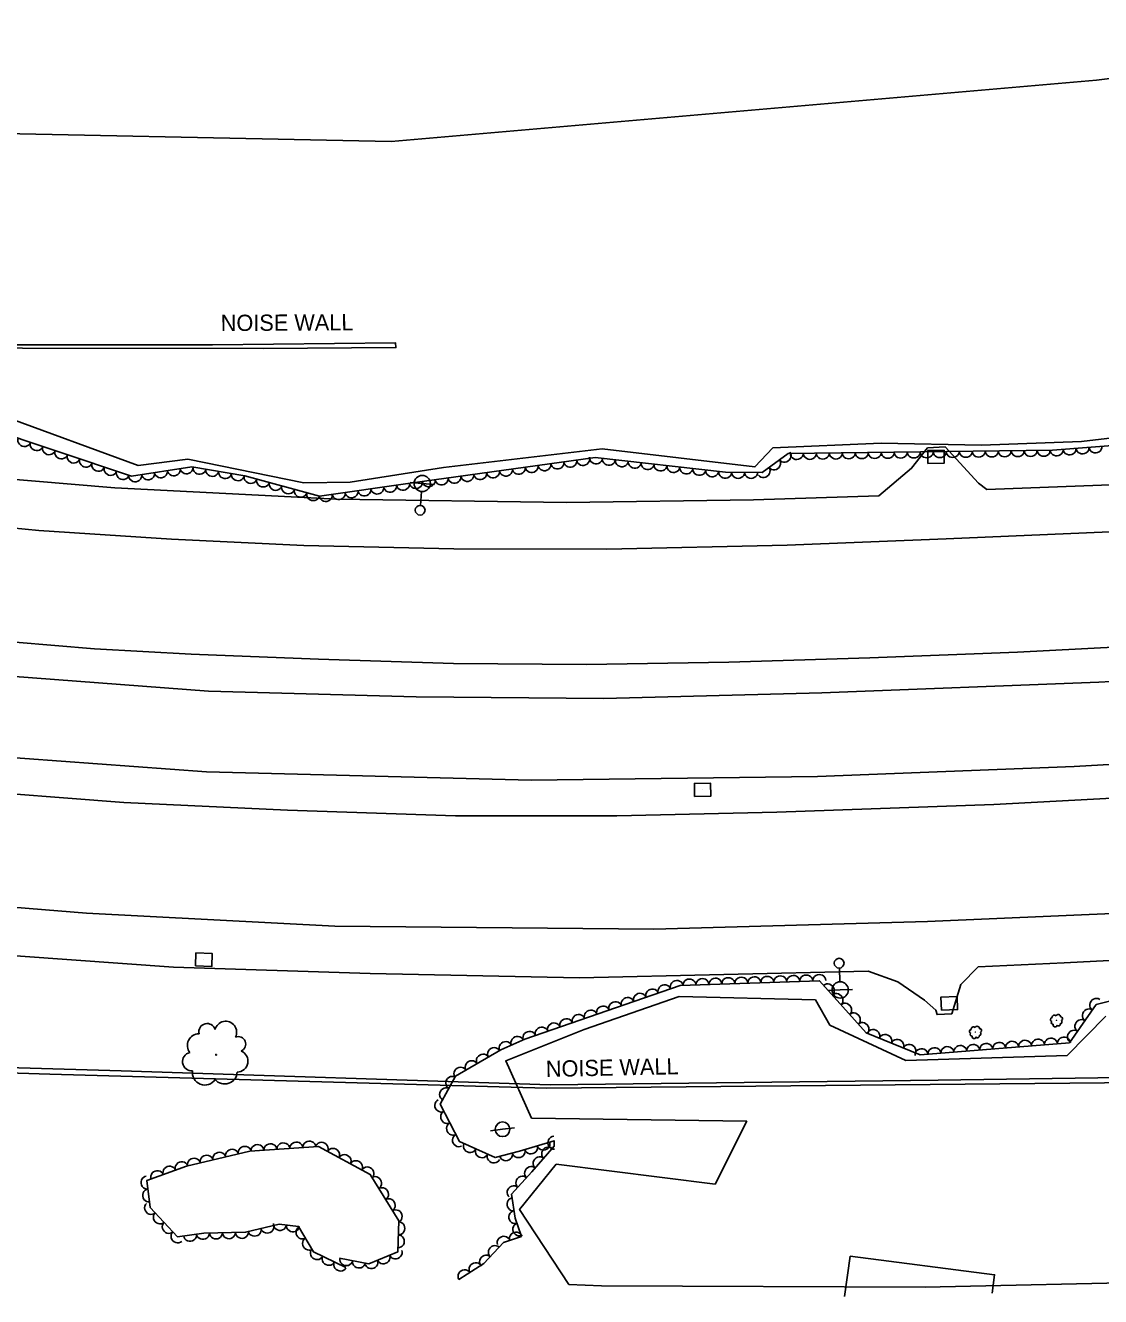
# Model space of a CAD drawing. Extents: x 1722896 to 1754269, y 648279 to 666297.
# Drawn here: x 1733286.4 to 1733617.5, y 649728 to 650119.6 of the extents above; entities that cross this region are included whole.
import ezdxf

# ---------------------------------------------------------------- set-up
doc = ezdxf.new("R2010")
doc.units = 0
for name, color, linetype in [('DESIGN - CENTERLINE - Proposed Text', 7, 'Continuous'), ('DESIGN - SCRATCH - User 1', 7, 'Continuous'), ('SURVEY - CENTERLINE - Preliminary', 7, 'Continuous'), ('SURVEY - CENTERLINE - Preliminary Text', 7, 'Continuous'), ('SURVEY - DRAINAGE - Natural Features', 7, 'Continuous'), ('SURVEY - DTM - Breaklines', 7, 'Continuous'), ('SURVEY - VEGETATION - Features with Text', 7, 'Continuous')]:
    doc.layers.add(name, color=color, linetype=linetype)

msp = doc.modelspace()

# ---------------------------------------------------------------- linework, layer by layer
at = {"layer": 'DESIGN - CENTERLINE - Proposed Text'}
msp.add_lwpolyline([(1733538.71, 649728), (1733540.43, 649740.4), (1733584.91, 649734.73), (1733584.11, 649729.03)], dxfattribs=at)
at = {"layer": 'DESIGN - SCRATCH - User 1'}
for points in [[(1732918.46, 650095.7), (1732990.78, 650071.44), (1733135.5, 650019.64), (1733170.75, 650018.4), (1733238.23, 650012.6), (1733238.7, 650020.63), (1733285.56, 650020.19), (1733359.67, 650020.02), (1733400.55, 650020.36), (1733400.38, 650021.81), (1733344.03, 650021.17), (1733272.52, 650021.18), (1733237.75, 650021.72), (1733237.19, 650014.12), (1733166.92, 650019.66), (1733135.98, 650020.42), (1733079.27, 650040.91), (1732995.25, 650070.89), (1732985.47, 650074.38), (1732919.02, 650097.38), (1732918.46, 650095.7)], [(1733708.07, 649796.67), (1733567.5, 649794.67), (1733447.99, 649793.18), (1733315.88, 649797.53), (1733210.77, 649800.66), (1733125.04, 649822.59), (1733011.58, 649851.6), (1732900.49, 649879.14), (1732799.81, 649904.59), (1732798.94, 649903.11)], [(1732798.94, 649903.11), (1732863.38, 649887.41), (1732951.01, 649865.35), (1733023.96, 649846.89), (1733118.03, 649823.14), (1733212.42, 649799.05), (1733294, 649796.53), (1733446.93, 649792.2), (1733629.48, 649793.9)]]:
    msp.add_lwpolyline(points, dxfattribs=at)
at = {"layer": 'SURVEY - CENTERLINE - Preliminary'}
for points in [[(1733249.81, 650086.9), (1733399.09, 650083.83), (1733616.24, 650102.67), (1733750.82, 650119.57)], [(1733642.17, 649995.02), (1733611.69, 649991.41), (1733580.83, 649990.28), (1733549.92, 649990.87), (1733516.58, 649989.45), (1733511.09, 649983.6), (1733464.01, 649989.19), (1733415.19, 649983.38), (1733386.43, 649978.84), (1733372.14, 649978.7), (1733336.43, 649986.01), (1733321.13, 649984.02), (1733279.13, 649999.38)], [(1733453.74, 649731.7), (1733438.6, 649754.79), (1733449.89, 649768.76), (1733498.81, 649762.64), (1733508.55, 649782.02), (1733442.33, 649783.01), (1733434.34, 649800.59), (1733458.46, 649810.3), (1733487.73, 649820.4), (1733529.7, 649819.44), (1733534.17, 649811.64), (1733557.55, 649800.75), (1733607.23, 649802.24), (1733619.14, 649814.38)], [(1733712.81, 649734.17), (1733563.48, 649730.91), (1733463.86, 649731.35), (1733453.74, 649731.7)]]:
    msp.add_lwpolyline(points, dxfattribs=at)
at = {"layer": 'SURVEY - CENTERLINE - Preliminary Text'}
for points in [[(1732884.23, 650076.17), (1732913.51, 650063.39), (1732976.87, 650040.9), (1733026.18, 650025.83), (1733038.06, 650031.39), (1733045.75, 650036.92), (1733051.82, 650034.88), (1733060.67, 650016.94), (1733102.57, 650006.66), (1733179.26, 649991.5), (1733218.23, 649985.76), (1733263.82, 649981.38), (1733313.93, 649977.09), (1733382.39, 649973.59), (1733453.08, 649972.61), (1733510.66, 649973.39), (1733549.29, 649974.69), (1733559.34, 649983.17), (1733564.28, 649989.43), (1733569.64, 649989.78), (1733579.99, 649978.6), (1733582.55, 649976.61), (1733628.65, 649978.32)], [(1733632.4, 649964.05), (1733569.97, 649961.42), (1733520.99, 649959.49), (1733465.51, 649958.19), (1733418.34, 649958.38), (1733372.14, 649959.4), (1733331.39, 649961.34), (1733290.54, 649963.98), (1733252.55, 649967.68), (1733214.23, 649972.07), (1733176.01, 649978.17), (1733138.91, 649984.71), (1733111.59, 649989.86), (1733075.7, 649997.91), (1733042.53, 650006.26), (1733001.92, 650017.92), (1732980.45, 650024.43), (1732948.58, 650035.49), (1732913.65, 650048.13), (1732876.04, 650062.89)], [(1734301.81, 649956.07), (1734220.48, 649950.88), (1734131.61, 649945.81), (1734021.54, 649939.36), (1733919.47, 649934.02), (1733832.29, 649929.05), (1733727.11, 649923.18), (1733616.99, 649917.25), (1733531.68, 649913.99), (1733464.56, 649912.26), (1733406.75, 649912.72), (1733342.81, 649914.54), (1733274.96, 649919.59), (1733238.81, 649922.74), (1733185.09, 649929.55), (1733133.9, 649938.69), (1733073.43, 649951.76), (1733022.34, 649964.08), (1732970.97, 649979.26), (1732924.79, 649995.09), (1732879.46, 650012.26), (1732856.98, 650021.29), (1732850.17, 650024.36)], [(1732910.74, 650011.51), (1732938.88, 650001.25), (1732978.51, 649988.35), (1733017.77, 649976.28), (1733057.36, 649966.4), (1733089.54, 649958.9), (1733122.15, 649951.97), (1733160.83, 649944.57), (1733191.08, 649940.04), (1733225.38, 649935.66), (1733270.98, 649930.64), (1733307.72, 649927.55), (1733337.44, 649925.94), (1733376.66, 649924.33), (1733418.23, 649922.99), (1733459.22, 649922.73), (1733503.07, 649923.42), (1733546.45, 649924.78), (1733592, 649926.51), (1733633.36, 649928.65)], [(1734306.6, 649930.59), (1734223.76, 649925.97), (1734108.71, 649919.44), (1734005.23, 649913.81), (1733895.38, 649907.1), (1733786.65, 649900.93), (1733684.61, 649895.58), (1733609.37, 649891.26), (1733530.4, 649888.22), (1733442.22, 649887.03), (1733342.17, 649889.65), (1733241.37, 649897), (1733146.01, 649910.52), (1733060.2, 649928.54), (1732976.3, 649951.63), (1732924.93, 649968.37), (1732878.63, 649985.6), (1732846.43, 649998.22), (1732835.13, 650003.3)], [(1732828.72, 649994.26), (1732832.8, 649992.38), (1732898.27, 649967.02), (1732935.22, 649953.75), (1732972.35, 649941.94), (1733018.58, 649928.26), (1733075.49, 649914.12), (1733116.55, 649905.32), (1733166.7, 649896.35), (1733213.16, 649889.74), (1733263.56, 649884.35), (1733316.73, 649880.2), (1733367.1, 649877.8), (1733418.88, 649876.14), (1733468.6, 649876.11), (1733517.84, 649877.2), (1733584.68, 649879.55), (1733659.52, 649883.6)], [(1734316.03, 649884.62), (1734227.04, 649879.8), (1734116.98, 649873.99), (1734008.92, 649867.44), (1733915.96, 649862.48), (1733822.6, 649857.33), (1733730.22, 649851.85), (1733644.88, 649847.07), (1733564.26, 649843.52), (1733479.91, 649841.18), (1733381.77, 649842.06), (1733305.26, 649846.16), (1733233.28, 649851.95), (1733189.33, 649857.53), (1733142.07, 649864.89), (1733082.71, 649876.45), (1733033.05, 649888.27), (1732982.37, 649901.96), (1732935.11, 649916.49), (1732876.61, 649937.35), (1732823.05, 649958.66), (1732808.59, 649965.1)], [(1732801.64, 649952.87), (1732820.37, 649944.25), (1732867.75, 649925.97), (1732908.14, 649911.21), (1732946.71, 649898.3), (1732999.39, 649882.77), (1733034.4, 649873.67), (1733105, 649857.11), (1733171.98, 649845.25), (1733226.84, 649838.36), (1733269.1, 649834.02), (1733332.07, 649829.44), (1733392.65, 649827.49), (1733457.05, 649826.23), (1733545.96, 649828.27), (1733555.15, 649824.91), (1733563.28, 649819.35), (1733566.84, 649816.28), (1733567.21, 649814.86), (1733571.69, 649815.15), (1733574.47, 649824.18), (1733579.83, 649829.56), (1733606.32, 649830.82), (1733646.3, 649832.85)]]:
    msp.add_lwpolyline(points, dxfattribs=at)
at = {"layer": 'SURVEY - DRAINAGE - Natural Features'}
for p, q in [((1733566.85, 649986.67), (1733566.85, 649986.67)), ((1733494.96, 649884.12), (1733494.96, 649884.12)), ((1733341.41, 649831.8), (1733341.41, 649831.8)), ((1733570.93, 649818.32), (1733570.93, 649818.32))]:
    msp.add_line(p, q, dxfattribs=at)
for points in [[(1733564.36, 649984.66), (1733564.34, 649988.66), (1733569.34, 649988.69), (1733569.36, 649984.69), (1733564.36, 649984.66)], [(1733492.49, 649882.09), (1733492.44, 649886.09), (1733497.44, 649886.15), (1733497.49, 649882.15), (1733492.49, 649882.09)], [(1733338.86, 649829.86), (1733338.96, 649833.86), (1733343.95, 649833.73), (1733343.86, 649829.73), (1733338.86, 649829.86)], [(1733568.51, 649816.21), (1733568.34, 649820.21), (1733573.34, 649820.42), (1733573.51, 649816.43), (1733568.51, 649816.21)]]:
    msp.add_lwpolyline(points, dxfattribs=at)
at = {"layer": 'SURVEY - DTM - Breaklines'}
for p, q in [((1733408.64, 649978.47), (1733404.9, 649978.76)), ((1733408.64, 649978.47), (1733412.38, 649978.18)), ((1733408.11, 649971.74), (1733408.44, 649975.98)), ((1733537.09, 649829.21), (1733537.25, 649824.96)), ((1733537.35, 649822.46), (1733533.6, 649822.32)), ((1733537.35, 649822.46), (1733541.1, 649822.61)), ((1733433.36, 649779.54), (1733429.64, 649779.11)), ((1733433.36, 649779.54), (1733437.09, 649779.97))]:
    msp.add_line(p, q, dxfattribs=at)
for centre, radius in [((1733408.64, 649978.47), 2.5), ((1733408, 649970.24), 1.5), ((1733537.03, 649830.7), 1.5), ((1733537.35, 649822.46), 2.5), ((1733433.36, 649779.54), 2.25)]:
    msp.add_circle(centre, radius, dxfattribs=at)
at = {"layer": 'SURVEY - VEGETATION - Features with Text'}
for points in [[(1733625.2, 649990.47), (1733602.68, 649988.77), (1733521.3, 649987.7), (1733513.3, 649981.88), (1733502.06, 649981.96), (1733461.89, 649986.43), (1733404.91, 649978.56), (1733377, 649974.53), (1733354.04, 649980.84), (1733337.68, 649983.59), (1733319.07, 649980.7), (1733273.29, 649996.05)], [(1733419.95, 649733.28), (1733427.6, 649738.18), (1733433.64, 649744.66), (1733439.16, 649746.55), (1733437.25, 649752.19), (1733436.16, 649759.55), (1733442.39, 649766.45), (1733449.31, 649774.34), (1733449.22, 649776.01), (1733438.55, 649772.77), (1733431.1, 649770.84), (1733420.07, 649775.73), (1733414.21, 649787.23), (1733418.9, 649795.9), (1733432.8, 649803.97), (1733440.22, 649807.3), (1733488.12, 649823.84), (1733530.99, 649825.31), (1733545.37, 649809.26), (1733561.95, 649802.44), (1733607.96, 649806.2), (1733616.2, 649818), (1733633.54, 649822.28)], [(1733385.16, 649736.91), (1733375.15, 649741.79), (1733370.58, 649749.63), (1733364.58, 649750.3), (1733354.23, 649747.82), (1733341.43, 649747.55), (1733333.32, 649746.38), (1733324.89, 649755.44), (1733323.83, 649763.72), (1733336.06, 649768.2), (1733355.56, 649772.77), (1733376.67, 649774.19), (1733392.61, 649765.61), (1733401.44, 649751.3), (1733401.12, 649741.75), (1733392.16, 649738.14), (1733383.18, 649739.79)]]:
    msp.add_lwpolyline(points, dxfattribs=at)
for centre, radius in [((1733603.95, 649813.08), 0.022), ((1733579.01, 649809.44), 0.022), ((1733345.16, 649802.49), 0.118)]:
    msp.add_circle(centre, radius, dxfattribs=at)
for centre, radius, start, end in [((1733342.4, 649809.55), 2.56, 15.5791, 192.8983), ((1733348.13, 649809.45), 3.36, 332.9604, 166.3801), ((1733602.71, 649813.31), 0.631, 97.432, 254.221), ((1733602.75, 649812.33), 0.433, 119.5482, 298.2938), ((1733603.34, 649813.99), 0.719, 46.4848, 184.009), ((1733604.47, 649814.19), 0.714, 357.3806, 153.2191), ((1733604.98, 649812.66), 0.679, 277.4746, 44.3203), ((1733605.3, 649813.64), 0.527, 287.6335, 102.6338), ((1733339.96, 649805.36), 3.63, 90.8662, 217.7118), ((1733577.77, 649809.67), 0.631, 97.432, 254.221), ((1733577.81, 649808.68), 0.433, 119.5482, 298.2938), ((1733578.4, 649810.34), 0.719, 46.4848, 184.009), ((1733578.6, 649808.08), 0.629, 159.5689, 352.9886), ((1733579.53, 649810.54), 0.714, 357.3806, 153.2191), ((1733579.67, 649808.18), 0.479, 202.1876, 19.5067), ((1733580.03, 649809.02), 0.679, 277.4746, 44.3203), ((1733580.36, 649809.99), 0.527, 287.6335, 102.6338), ((1733603.54, 649811.73), 0.629, 159.5689, 352.9886), ((1733604.61, 649811.83), 0.479, 202.1876, 19.5067), ((1733351.98, 649805.77), 2.31, 292.9398, 111.6854), ((1733337.62, 649800.38), 2.81, 101.0251, 276.0254), ((1733351.6, 649800.52), 3.37, 270.8236, 67.6125), ((1733341.69, 649796.97), 3.82, 170.7722, 326.6107), ((1733347.82, 649797.33), 3.84, 219.8763, 357.4006)]:
    msp.add_arc(centre, radius, start, end, dxfattribs=at)
for centre, major_axis in [((1733286.09, 649991.76), (-1.9, 0.64)), ((1733289.88, 649990.49), (-1.9, 0.64)), ((1733293.68, 649989.22), (-1.9, 0.64)), ((1733297.47, 649987.95), (-1.9, 0.64)), ((1733564.01, 649988.26), (-2, -0.03)), ((1733568.01, 649988.31), (-2, -0.03)), ((1733572.01, 649988.37), (-2, -0.03)), ((1733576.01, 649988.42), (-2, -0.03)), ((1733580.01, 649988.47), (-2, -0.03)), ((1733584.01, 649988.52), (-2, -0.03)), ((1733588.01, 649988.58), (-2, -0.03)), ((1733592.01, 649988.63), (-2, -0.03)), ((1733596.01, 649988.68), (-2, -0.03)), ((1733600.01, 649988.73), (-2, -0.03)), ((1733604.01, 649988.87), (-1.99, -0.15)), ((1733607.99, 649989.17), (-1.99, -0.15)), ((1733611.98, 649989.47), (-1.99, -0.15)), ((1733615.97, 649989.77), (-1.99, -0.15)), ((1733301.26, 649986.67), (-1.9, 0.64)), ((1733305.05, 649985.4), (-1.9, 0.64)), ((1733308.85, 649984.13), (-1.9, 0.64)), ((1733446.3, 649984.27), (-1.98, -0.27)), ((1733450.27, 649984.82), (-1.98, -0.27)), ((1733454.23, 649985.37), (-1.98, -0.27)), ((1733458.19, 649985.91), (-1.98, -0.27)), ((1733462.15, 649986.4), (-1.99, 0.22)), ((1733466.13, 649985.95), (-1.99, 0.22)), ((1733470.1, 649985.51), (-1.99, 0.22)), ((1733474.08, 649985.07), (-1.99, 0.22)), ((1733478.06, 649984.63), (-1.99, 0.22)), ((1733482.03, 649984.19), (-1.99, 0.22)), ((1733517.03, 649984.59), (-1.62, -1.18)), ((1733520.26, 649986.95), (-1.62, -1.18)), ((1733524.02, 649987.73), (-2, -0.03)), ((1733528.02, 649987.79), (-2, -0.03)), ((1733532.02, 649987.84), (-2, -0.03)), ((1733536.02, 649987.89), (-2, -0.03)), ((1733540.01, 649987.95), (-2, -0.03)), ((1733544.01, 649988), (-2, -0.03)), ((1733548.01, 649988.05), (-2, -0.03)), ((1733552.01, 649988.1), (-2, -0.03)), ((1733556.01, 649988.16), (-2, -0.03)), ((1733560.01, 649988.21), (-2, -0.03)), ((1733312.64, 649982.86), (-1.9, 0.64)), ((1733316.43, 649981.59), (-1.9, 0.64)), ((1733320.27, 649980.89), (-1.98, -0.31)), ((1733324.23, 649981.5), (-1.98, -0.31)), ((1733328.18, 649982.12), (-1.98, -0.31)), ((1733332.13, 649982.73), (-1.98, -0.31)), ((1733336.08, 649983.35), (-1.98, -0.31)), ((1733340.03, 649983.2), (-1.97, 0.33)), ((1733343.98, 649982.53), (-1.97, 0.33)), ((1733347.92, 649981.87), (-1.97, 0.33)), ((1733351.86, 649981.2), (-1.97, 0.33)), ((1733355.77, 649980.36), (-1.93, 0.53)), ((1733418.57, 649980.45), (-1.98, -0.27)), ((1733422.53, 649980.99), (-1.98, -0.27)), ((1733426.49, 649981.54), (-1.98, -0.27)), ((1733430.45, 649982.09), (-1.98, -0.27)), ((1733434.42, 649982.63), (-1.98, -0.27)), ((1733438.38, 649983.18), (-1.98, -0.27)), ((1733442.34, 649983.73), (-1.98, -0.27)), ((1733486.01, 649983.74), (-1.99, 0.22)), ((1733489.98, 649983.3), (-1.99, 0.22)), ((1733493.96, 649982.86), (-1.99, 0.22)), ((1733497.93, 649982.42), (-1.99, 0.22)), ((1733501.91, 649981.98), (-1.99, 0.22)), ((1733505.91, 649981.93), (-2, 0.01)), ((1733509.91, 649981.91), (-2, 0.01)), ((1733513.79, 649982.24), (-1.62, -1.18)), ((1733359.63, 649979.3), (-1.93, 0.53)), ((1733363.48, 649978.25), (-1.93, 0.53)), ((1733367.34, 649977.19), (-1.93, 0.53)), ((1733371.2, 649976.13), (-1.93, 0.53)), ((1733390.84, 649976.53), (-1.98, -0.29)), ((1733394.8, 649977.1), (-1.98, -0.29)), ((1733398.76, 649977.67), (-1.98, -0.29)), ((1733402.72, 649978.24), (-1.98, -0.29)), ((1733406.68, 649978.8), (-1.98, -0.27)), ((1733410.64, 649979.35), (-1.98, -0.27)), ((1733414.6, 649979.9), (-1.98, -0.27)), ((1733375.06, 649975.07), (-1.93, 0.53)), ((1733378.96, 649974.82), (-1.98, -0.29)), ((1733382.92, 649975.39), (-1.98, -0.29)), ((1733386.88, 649975.96), (-1.98, -0.29)), ((1733483.22, 649822.15), (1.89, 0.65)), ((1733487, 649823.46), (1.89, 0.65)), ((1733490.93, 649823.94), (2, 0.07)), ((1733494.93, 649824.08), (2, 0.07)), ((1733498.93, 649824.21), (2, 0.07)), ((1733502.92, 649824.35), (2, 0.07)), ((1733506.92, 649824.49), (2, 0.07)), ((1733510.92, 649824.62), (2, 0.07)), ((1733514.92, 649824.76), (2, 0.07)), ((1733518.91, 649824.89), (2, 0.07)), ((1733522.91, 649825.03), (2, 0.07)), ((1733526.91, 649825.17), (2, 0.07)), ((1733530.91, 649825.3), (2, 0.07)), ((1733533.6, 649822.39), (1.33, -1.49)), ((1733471.87, 649818.23), (1.89, 0.65)), ((1733475.65, 649819.54), (1.89, 0.65)), ((1733479.44, 649820.85), (1.89, 0.65)), ((1733536.27, 649819.41), (1.33, -1.49)), ((1733616.13, 649817.91), (1.15, 1.64)), ((1733460.53, 649814.32), (1.89, 0.65)), ((1733464.31, 649815.62), (1.89, 0.65)), ((1733468.09, 649816.93), (1.89, 0.65)), ((1733538.94, 649816.43), (1.33, -1.49)), ((1733613.84, 649814.63), (1.15, 1.64)), ((1733449.19, 649810.4), (1.89, 0.65)), ((1733452.97, 649811.7), (1.89, 0.65)), ((1733456.75, 649813.01), (1.89, 0.65)), ((1733541.61, 649813.45), (1.33, -1.49)), ((1733544.28, 649810.47), (1.33, -1.49)), ((1733611.55, 649811.35), (1.15, 1.64)), ((1733437.93, 649806.27), (1.82, 0.82)), ((1733441.63, 649807.79), (1.89, 0.65)), ((1733445.41, 649809.09), (1.89, 0.65)), ((1733547.56, 649808.36), (1.85, -0.76)), ((1733551.26, 649806.84), (1.85, -0.76)), ((1733609.26, 649808.07), (1.15, 1.64)), ((1733430.74, 649802.78), (1.73, 1.01)), ((1733434.28, 649804.64), (1.82, 0.82)), ((1733554.96, 649805.31), (1.85, -0.76)), ((1733558.66, 649803.79), (1.85, -0.76)), ((1733562.39, 649802.47), (1.99, 0.16)), ((1733566.38, 649802.8), (1.99, 0.16)), ((1733570.37, 649803.12), (1.99, 0.16)), ((1733574.35, 649803.45), (1.99, 0.16)), ((1733578.34, 649803.78), (1.99, 0.16)), ((1733582.33, 649804.1), (1.99, 0.16)), ((1733586.31, 649804.43), (1.99, 0.16)), ((1733590.3, 649804.76), (1.99, 0.16)), ((1733594.29, 649805.08), (1.99, 0.16)), ((1733598.27, 649805.41), (1.99, 0.16)), ((1733602.26, 649805.73), (1.99, 0.16)), ((1733606.25, 649806.06), (1.99, 0.16)), ((1733423.83, 649798.76), (1.73, 1.01)), ((1733427.28, 649800.77), (1.73, 1.01)), ((1733420.37, 649796.75), (1.73, 1.01)), ((1733415.9, 649790.35), (0.95, 1.76)), ((1733417.8, 649793.87), (0.95, 1.76)), ((1733414.41, 649786.83), (-0.91, 1.78)), ((1733416.23, 649783.27), (-0.91, 1.78)), ((1733418.04, 649779.7), (-0.91, 1.78)), ((1733419.86, 649776.14), (-0.91, 1.78)), ((1733449.25, 649775.38), (-0.11, 2)), ((1733350.05, 649771.48), (1.95, 0.46)), ((1733353.95, 649772.39), (1.95, 0.46)), ((1733357.9, 649772.92), (2, 0.13)), ((1733361.89, 649773.19), (2, 0.13)), ((1733365.88, 649773.46), (2, 0.13)), ((1733369.87, 649773.73), (2, 0.13)), ((1733373.86, 649774), (2, 0.13)), ((1733377.71, 649773.63), (1.76, -0.95)), ((1733381.24, 649771.73), (1.76, -0.95)), ((1733423.3, 649774.29), (-1.83, 0.81)), ((1733426.96, 649772.68), (-1.83, 0.81)), ((1733438.34, 649772.72), (-1.94, -0.5)), ((1733442.17, 649773.87), (-1.91, -0.58)), ((1733445.99, 649775.03), (-1.91, -0.58)), ((1733447.36, 649772.12), (1.32, 1.5)), ((1733334.53, 649767.64), (1.88, 0.69)), ((1733338.37, 649768.74), (1.95, 0.46)), ((1733342.26, 649769.66), (1.95, 0.46)), ((1733346.16, 649770.57), (1.95, 0.46)), ((1733384.76, 649769.84), (1.76, -0.95)), ((1733388.28, 649767.94), (1.76, -0.95)), ((1733430.62, 649771.06), (-1.83, 0.81)), ((1733434.46, 649771.72), (-1.94, -0.5)), ((1733444.72, 649769.11), (1.32, 1.5)), ((1733323.91, 649763.12), (-0.25, 1.98)), ((1733327.02, 649764.89), (1.88, 0.69)), ((1733330.78, 649766.27), (1.88, 0.69)), ((1733391.8, 649766.04), (1.76, -0.95)), ((1733394.23, 649762.99), (1.05, -1.7)), ((1733439.4, 649763.14), (1.34, 1.48)), ((1733442.08, 649766.11), (1.34, 1.48)), ((1733396.33, 649759.58), (1.05, -1.7)), ((1733436.72, 649760.17), (1.34, 1.48)), ((1733324.42, 649759.15), (-0.25, 1.98)), ((1733398.43, 649756.18), (1.05, -1.7)), ((1733436.63, 649756.42), (-0.29, 1.98)), ((1733325.06, 649755.25), (-1.36, 1.46)), ((1733327.79, 649752.32), (-1.36, 1.46)), ((1733400.53, 649752.77), (1.05, -1.7)), ((1733437.21, 649752.46), (-0.29, 1.98)), ((1733330.52, 649749.4), (-1.36, 1.46)), ((1733360.93, 649749.42), (-1.94, -0.47)), ((1733364.82, 649750.27), (-1.99, 0.22)), ((1733368.8, 649749.83), (-1.99, 0.22)), ((1733371.69, 649747.72), (-1.01, 1.73)), ((1733401.37, 649749.03), (-0.07, -2)), ((1733438.44, 649748.66), (-0.64, 1.89)), ((1733333.24, 649746.47), (-1.36, 1.46)), ((1733337.16, 649746.94), (-1.98, -0.28)), ((1733341.12, 649747.51), (-1.98, -0.28)), ((1733345.12, 649747.63), (-2, -0.04)), ((1733349.12, 649747.71), (-2, -0.04)), ((1733353.12, 649747.8), (-2, -0.04)), ((1733357.04, 649748.49), (-1.94, -0.47)), ((1733373.71, 649744.26), (-1.01, 1.73)), ((1733401.23, 649745.04), (-0.07, -2)), ((1733433.7, 649744.68), (1.89, 0.65)), ((1733437.48, 649745.97), (1.89, 0.65)), ((1733376.17, 649741.29), (-1.8, 0.88)), ((1733400.46, 649741.48), (-1.85, -0.75)), ((1733430.95, 649741.78), (1.36, 1.46)), ((1733379.76, 649739.54), (-1.8, 0.88)), ((1733383.36, 649737.78), (-1.8, 0.88)), ((1733385.23, 649739.41), (-1.97, 0.36)), ((1733389.16, 649738.69), (-1.97, 0.36)), ((1733393.04, 649738.49), (-1.85, -0.75)), ((1733396.75, 649739.99), (-1.85, -0.75)), ((1733425.01, 649736.52), (1.68, 1.08)), ((1733428.23, 649738.85), (1.36, 1.46)), ((1733421.64, 649734.36), (1.68, 1.08))]:
    msp.add_ellipse(centre, major_axis=major_axis, ratio=0.940188, start_param=0, end_param=3.141593, dxfattribs=at)

# ---------------------------------------------------------------- texts
at = {"layer": 'DESIGN - SCRATCH - User 1'}
for rotation, p in [(0.3356, (1733346.6, 650025.42)), (1.2022, (1733446.75, 649795.64))]:
    msp.add_text('NOISE WALL', height=5, rotation=rotation, dxfattribs=at).set_placement(p)

doc.saveas('drawing.dxf')
